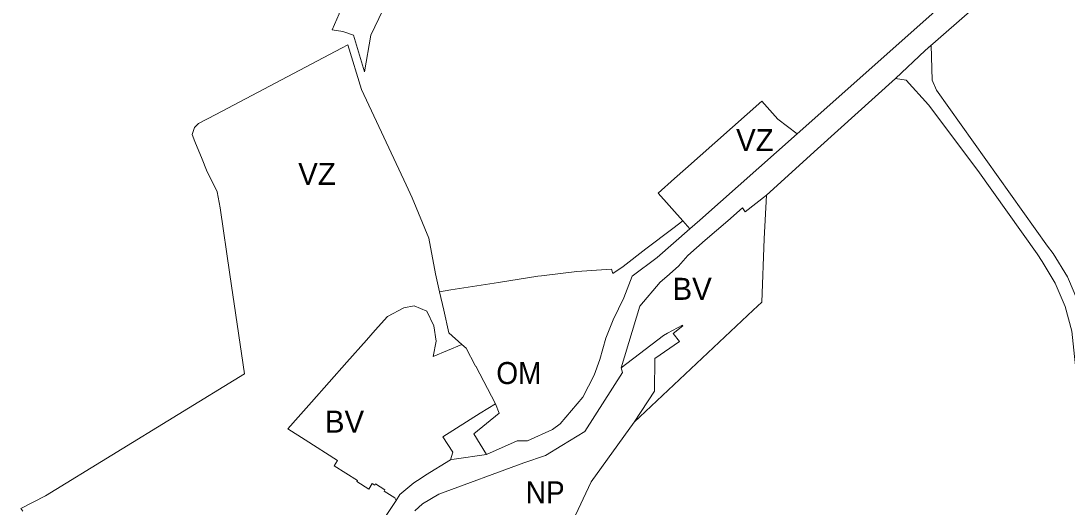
# Model space of a CAD drawing. Extents: x -650451 to -642268, y -1075216 to -1066610.
# Drawn here: x -646150 to -645580, y -1068657 to -1068392 of the extents above; entities that cross this region are included whole.
import ezdxf

# ---------------------------------------------------------------- set-up
doc = ezdxf.new("R2010")
doc.units = 0
doc.header["$LTSCALE"] = 4.8
for name, color, linetype, lineweight in [('12', 7, 'Continuous', 13), ('15', 7, 'Continuous', 13), ('24', 7, 'Continuous', 13), ('3', 7, 'Continuous', 13), ('36', 7, 'Continuous', 13), ('46', 7, 'Continuous', 13), ('48', 7, 'Continuous', 13)]:
    doc.layers.add(name, color=color, linetype=linetype, lineweight=lineweight)
doc.layers.add('62', color=7, linetype='Continuous')

msp = doc.modelspace()

# ---------------------------------------------------------------- linework, layer by layer
at = {"layer": '12'}
for points in [[(-645922.02, -1068539.96), (-645915.92, -1068538.99), (-645890.02, -1068534.9), (-645868.47, -1068531.53), (-645866.58, -1068531.3), (-645847.4, -1068528.93), (-645828.52, -1068527.64), (-645827.73, -1068530.12), (-645822.09, -1068526.17), (-645809.67, -1068516.54), (-645795.14, -1068505.6), (-645789.58, -1068501.42), (-645785.72, -1068505.75)], [(-645785.72, -1068505.75), (-645803.67, -1068521.32), (-645817.13, -1068531.51), (-645821.8, -1068543.22), (-645827.54, -1068555.34), (-645831.5, -1068565.29), (-645834.88, -1068576.82), (-645837.87, -1068585.42), (-645844.03, -1068597.45), (-645856.41, -1068612.02), (-645860.62, -1068615.07), (-645874.15, -1068621.18), (-645879.74, -1068621.23), (-645896.46, -1068628.59)], [(-645909.89, -1068568.71), (-645916.99, -1068562.41), (-645919.73, -1068549.98), (-645922.02, -1068539.96)], [(-645891.57, -1068600.96), (-645902.31, -1068580.46), (-645902.51, -1068580.52), (-645902.68, -1068580.19), (-645907.65, -1068570.7), (-645909.89, -1068568.71)], [(-645896.46, -1068628.59), (-645903.39, -1068617.33), (-645889.69, -1068606.15), (-645891.57, -1068600.96)]]:
    msp.add_lwpolyline(points, dxfattribs=at)
at = {"layer": '15'}
for points in [[(-645657.63, -1068408.53), (-645654.34, -1068405.65), (-645653.87, -1068424.71), (-645651.53, -1068430.1), (-645591.03, -1068515.22), (-645587.94, -1068519.19), (-645580.2, -1068531.93), (-645576.6, -1068540.35), (-645574.36, -1068545.66), (-645570.55, -1068560.09), (-645568.86, -1068574.89), (-645568.88, -1068579.93), (-645563.42, -1068709.35), (-645557.97, -1068838.77), (-645557.27, -1068843.66), (-645556.12, -1068850.33), (-645553.29, -1068856.55), (-645552.302, -1068859.444)], [(-645632.76, -1068904.96), (-645605.99, -1068885.11), (-645567.83, -1068857.79), (-645564.25, -1068849.99), (-645565.26, -1068844.12), (-645564.97, -1068839.07), (-645565.34, -1068825.58), (-645568.99, -1068739.04), (-645571.75, -1068677.77), (-645575.86, -1068580.22), (-645576.29, -1068575.28), (-645577.8, -1068561.45), (-645581.4, -1068548.08), (-645586.82, -1068535.33), (-645594.04, -1068523.44), (-645596.74, -1068519.27), (-645628.94, -1068473.97), (-645655.81, -1068438.19), (-645668.04, -1068424.72), (-645673.86, -1068423.84), (-645657.63, -1068408.53)], [(-645916.18, -1068631.57), (-645914.86, -1068627.46), (-645920.28, -1068619.1), (-645899.88, -1068606.17), (-645891.57, -1068600.96)], [(-645891.57, -1068600.96), (-645889.69, -1068606.15), (-645903.39, -1068617.33), (-645896.46, -1068628.59)], [(-645896.46, -1068628.59), (-645914.12, -1068631.26), (-645916.18, -1068631.57)]]:
    msp.add_lwpolyline(points, dxfattribs=at)
at = {"layer": '24'}
for points in [[(-645228.257, -1068033.102), (-645232.31, -1068036.91), (-645249.9, -1068051.45), (-645342.79, -1068132.81), (-645592.08, -1068351.12), (-645657.63, -1068408.53), (-645673.86, -1068423.84)], [(-645727.32, -1068453.86), (-645644.17, -1068379.88), (-645600.441, -1068340.017)], [(-645673.86, -1068423.84), (-645716.22, -1068462.08), (-645744.06, -1068487.4)], [(-645785.72, -1068505.75), (-645780.28, -1068501.04), (-645727.32, -1068453.86)], [(-645744.06, -1068487.4), (-645755.63, -1068496.42), (-645757.11, -1068494.29), (-645765.18, -1068501.29), (-645777.39, -1068511.9), (-645786.82, -1068520.27), (-645791.92, -1068526.09), (-645798.33, -1068531.67), (-645801.91, -1068534.79), (-645813.08, -1068547.87), (-645823.18, -1068581.36)], [(-645896.46, -1068628.59), (-645879.74, -1068621.23), (-645874.15, -1068621.18), (-645860.62, -1068615.07), (-645856.41, -1068612.02), (-645844.03, -1068597.45), (-645837.87, -1068585.42), (-645834.88, -1068576.82), (-645831.5, -1068565.29), (-645827.54, -1068555.34), (-645821.8, -1068543.22), (-645817.13, -1068531.51), (-645803.67, -1068521.32), (-645785.72, -1068505.75)], [(-645823.18, -1068581.36), (-645822.53, -1068584.02), (-645843.03, -1068616.2), (-645855.41, -1068623.7), (-645864.4, -1068629.15), (-645876.17, -1068633.1), (-645922.43, -1068650.3), (-645931.4, -1068655.44), (-645935.44, -1068659.31)], [(-645916.18, -1068631.57), (-645914.12, -1068631.26), (-645896.46, -1068628.59)], [(-645945.75, -1068653.7), (-645943.63, -1068650.37), (-645936.08, -1068644.03), (-645932.11, -1068641.45), (-645929.72, -1068639.9), (-645916.18, -1068631.57)], [(-646081.15, -1068787.09), (-646024.22, -1068764.13), (-646023.16, -1068763.37), (-646006.77, -1068742.76), (-645990.79, -1068722.02), (-645978.4, -1068702.69), (-645976.09, -1068699.08), (-645964.19, -1068680.5), (-645963.17, -1068679.86), (-645945.75, -1068653.7)]]:
    msp.add_lwpolyline(points, dxfattribs=at)
at = {"layer": '3'}
for points in [[(-645823.18, -1068581.36), (-645813.08, -1068547.87), (-645801.91, -1068534.79), (-645798.33, -1068531.67), (-645791.92, -1068526.09), (-645786.82, -1068520.27), (-645777.39, -1068511.9), (-645765.18, -1068501.29), (-645757.11, -1068494.29), (-645755.63, -1068496.42), (-645744.06, -1068487.4)], [(-645744.06, -1068487.4), (-645745.39, -1068511.09), (-645746.63, -1068545.61), (-645751.23, -1068549.94), (-645816.02, -1068611.01)], [(-645945.75, -1068653.7), (-645946.37, -1068652.24), (-645952.28, -1068648.55), (-645951.87, -1068647.86), (-645956.91, -1068644.61), (-645957.36, -1068645.33), (-645958.67, -1068644.5), (-645960.63, -1068647.57), (-645967.14, -1068643.41), (-645966.82, -1068642.9), (-645979.52, -1068634.8), (-645977.65, -1068631.85), (-645995.17, -1068620.64), (-646004.63, -1068614.59), (-645999.05, -1068608.31), (-645991.78, -1068600.12), (-645972.49, -1068578.4), (-645961.86, -1068566.44), (-645957.04, -1068560.99), (-645950.32, -1068553.38), (-645941.5, -1068548.73), (-645935.86, -1068547.57), (-645929.07, -1068550.59), (-645925.25, -1068558.49), (-645923.96, -1068566.95), (-645925.53, -1068575.33), (-645909.89, -1068568.71)], [(-645816.02, -1068611.01), (-645805.04, -1068594.17), (-645804.84, -1068576.37), (-645791.47, -1068567.01), (-645794.88, -1068562.71), (-645789.55, -1068558.56), (-645789.84, -1068558.19), (-645798.03, -1068562.46), (-645800.22, -1068563.89), (-645823.18, -1068581.36)], [(-645909.89, -1068568.71), (-645907.65, -1068570.7), (-645902.68, -1068580.19), (-645902.51, -1068580.52), (-645902.31, -1068580.46), (-645891.57, -1068600.96)], [(-645891.57, -1068600.96), (-645899.88, -1068606.17), (-645920.28, -1068619.1), (-645914.86, -1068627.46), (-645916.18, -1068631.57)], [(-645916.18, -1068631.57), (-645929.72, -1068639.9), (-645932.11, -1068641.45), (-645936.08, -1068644.03), (-645943.63, -1068650.37), (-645945.75, -1068653.7)]]:
    msp.add_lwpolyline(points, dxfattribs=at)
at = {"layer": '36'}
for points in [[(-646149.04, -1068659.6), (-646149.99, -1068658.12), (-646136.66, -1068651.17), (-646028.19, -1068584.65), (-646036.27, -1068530.56), (-646041.44, -1068494.27), (-646043.13, -1068485.53), (-646048.96, -1068473.76), (-646051.28, -1068467.73), (-646055.39, -1068458.11), (-646056.77, -1068454.35), (-646055.56, -1068450.55), (-646053.26, -1068448.37), (-646043.93, -1068443.44), (-645975.47, -1068407.25), (-645971.94, -1068405.38), (-645964.53, -1068429.83), (-645964.51, -1068429.88), (-645940.28, -1068481.66), (-645936.95, -1068488.76), (-645927.86, -1068510.76), (-645924.25, -1068530.17), (-645922.02, -1068539.96)], [(-645789.58, -1068501.42), (-645803.01, -1068486.33), (-645794.06, -1068478.36), (-645788.09, -1068473.04), (-645746.68, -1068436.15), (-645737.89, -1068446.04), (-645727.32, -1068453.86)], [(-645727.32, -1068453.86), (-645780.28, -1068501.04), (-645785.72, -1068505.75), (-645789.58, -1068501.42)], [(-645922.02, -1068539.96), (-645919.73, -1068549.98), (-645916.99, -1068562.41), (-645909.89, -1068568.71)], [(-645909.89, -1068568.71), (-645925.53, -1068575.33), (-645923.96, -1068566.95), (-645925.25, -1068558.49), (-645929.07, -1068550.59), (-645935.86, -1068547.57), (-645941.5, -1068548.73), (-645950.32, -1068553.38), (-645957.04, -1068560.99), (-645961.86, -1068566.44), (-645972.49, -1068578.4), (-645991.78, -1068600.12), (-645999.05, -1068608.31), (-646004.63, -1068614.59), (-645995.17, -1068620.64), (-645977.65, -1068631.85), (-645979.52, -1068634.8), (-645966.82, -1068642.9), (-645967.14, -1068643.41), (-645960.63, -1068647.57), (-645958.67, -1068644.5), (-645957.36, -1068645.33), (-645956.91, -1068644.61), (-645951.87, -1068647.86), (-645952.28, -1068648.55), (-645946.37, -1068652.24), (-645945.75, -1068653.7)], [(-645945.75, -1068653.7), (-645963.17, -1068679.86), (-645964.19, -1068680.5), (-645976.09, -1068699.08), (-645978.4, -1068702.69), (-645990.79, -1068722.02), (-646006.77, -1068742.76), (-646023.16, -1068763.37), (-646024.22, -1068764.13), (-646081.15, -1068787.09)]]:
    msp.add_lwpolyline(points, dxfattribs=at)
at = {"layer": '46'}
for points in [[(-645657.63, -1068408.53), (-645592.08, -1068351.12), (-645342.79, -1068132.81), (-645249.9, -1068051.45), (-645232.31, -1068036.91), (-645228.257, -1068033.102)], [(-645917.44, -1068129.99), (-645938.87, -1068193.06), (-645951.35, -1068230.61), (-645955.63, -1068243.79), (-645959.15, -1068257.17), (-645961.93, -1068270.74), (-645963.94, -1068284.44), (-645975.46, -1068381.74), (-645976.72, -1068388.53), (-645980.61, -1068397.35), (-645974.67, -1068398.28), (-645968.86, -1068400.15), (-645962.86, -1068420.15), (-645959.41, -1068400.16), (-645952.92, -1068386.53), (-645929.29, -1068342.91), (-645914.12, -1068313.54), (-645899.73, -1068289.25), (-645886.28, -1068264.22), (-645883.87, -1068256.88), (-645872.64, -1068238.08)], [(-645600.441, -1068340.017), (-645644.17, -1068379.88), (-645727.32, -1068453.86)], [(-645922.02, -1068539.96), (-645924.25, -1068530.17), (-645927.86, -1068510.76), (-645936.95, -1068488.76), (-645940.28, -1068481.66), (-645964.51, -1068429.88), (-645964.53, -1068429.83), (-645971.94, -1068405.38), (-645975.47, -1068407.25), (-646043.93, -1068443.44), (-646053.26, -1068448.37), (-646055.56, -1068450.55), (-646056.77, -1068454.35), (-646055.39, -1068458.11), (-646051.28, -1068467.73), (-646048.96, -1068473.76), (-646043.13, -1068485.53), (-646041.44, -1068494.27), (-646036.27, -1068530.56), (-646028.19, -1068584.65), (-646136.66, -1068651.17), (-646149.99, -1068658.12), (-646149.04, -1068659.6)], [(-645552.302, -1068859.444), (-645553.29, -1068856.55), (-645556.12, -1068850.33), (-645557.27, -1068843.66), (-645557.97, -1068838.77), (-645563.42, -1068709.35), (-645568.88, -1068579.93), (-645568.86, -1068574.89), (-645570.55, -1068560.09), (-645574.36, -1068545.66), (-645576.6, -1068540.35), (-645580.2, -1068531.93), (-645587.94, -1068519.19), (-645591.03, -1068515.22), (-645651.53, -1068430.1), (-645653.87, -1068424.71), (-645654.34, -1068405.65), (-645657.63, -1068408.53)], [(-645744.06, -1068487.4), (-645716.22, -1068462.08), (-645673.86, -1068423.84)], [(-645673.86, -1068423.84), (-645668.04, -1068424.72), (-645655.81, -1068438.19), (-645628.94, -1068473.97), (-645596.74, -1068519.27), (-645594.04, -1068523.44), (-645586.82, -1068535.33), (-645581.4, -1068548.08), (-645577.8, -1068561.45), (-645576.29, -1068575.28), (-645575.86, -1068580.22), (-645571.75, -1068677.77), (-645568.99, -1068739.04), (-645565.34, -1068825.58), (-645564.97, -1068839.07), (-645565.26, -1068844.12), (-645564.25, -1068849.99), (-645567.83, -1068857.79), (-645605.99, -1068885.11), (-645632.76, -1068904.96), (-645646.49, -1068892.56)], [(-645727.32, -1068453.86), (-645737.89, -1068446.04), (-645746.68, -1068436.15), (-645788.09, -1068473.04), (-645794.06, -1068478.36), (-645803.01, -1068486.33), (-645789.58, -1068501.42)], [(-645816.02, -1068611.01), (-645751.23, -1068549.94), (-645746.63, -1068545.61), (-645745.39, -1068511.09), (-645744.06, -1068487.4)], [(-645789.58, -1068501.42), (-645795.14, -1068505.6), (-645809.67, -1068516.54), (-645822.09, -1068526.17), (-645827.73, -1068530.12), (-645828.52, -1068527.64), (-645847.4, -1068528.93), (-645866.58, -1068531.3), (-645868.47, -1068531.53), (-645890.02, -1068534.9), (-645915.92, -1068538.99), (-645922.02, -1068539.96)], [(-645868.98, -1068731.71), (-645860.91, -1068689.17), (-645839.55, -1068643.47), (-645816.02, -1068611.01)]]:
    msp.add_lwpolyline(points, dxfattribs=at)
at = {"layer": '48'}
for points in [[(-645823.18, -1068581.36), (-645800.22, -1068563.89), (-645798.03, -1068562.46), (-645789.84, -1068558.19), (-645789.55, -1068558.56), (-645794.88, -1068562.71), (-645791.47, -1068567.01), (-645804.84, -1068576.37), (-645805.04, -1068594.17), (-645816.02, -1068611.01)], [(-645935.44, -1068659.31), (-645931.4, -1068655.44), (-645922.43, -1068650.3), (-645876.17, -1068633.1), (-645864.4, -1068629.15), (-645855.41, -1068623.7), (-645843.03, -1068616.2), (-645822.53, -1068584.02), (-645823.18, -1068581.36)], [(-645816.02, -1068611.01), (-645839.55, -1068643.47), (-645860.91, -1068689.17), (-645868.98, -1068731.71)]]:
    msp.add_lwpolyline(points, dxfattribs=at)

# ---------------------------------------------------------------- texts
at = {"layer": '62'}
for s, p in [('VZ', (-645760.623, -1068463.378)), ('VZ', (-645999.038, -1068481.772)), ('BV', (-645795.251, -1068544.393)), ('BV', (-645984.519, -1068616.73))]:
    msp.add_text(s, height=12, dxfattribs=at).set_placement(p)
at = {"layer": '62', "width": 0.95}
for s, p in [('OM', (-645891.148, -1068590.263)), ('NP', (-645875.13, -1068655.285))]:
    msp.add_text(s, height=12, dxfattribs=at).set_placement(p)

doc.saveas('drawing.dxf')
